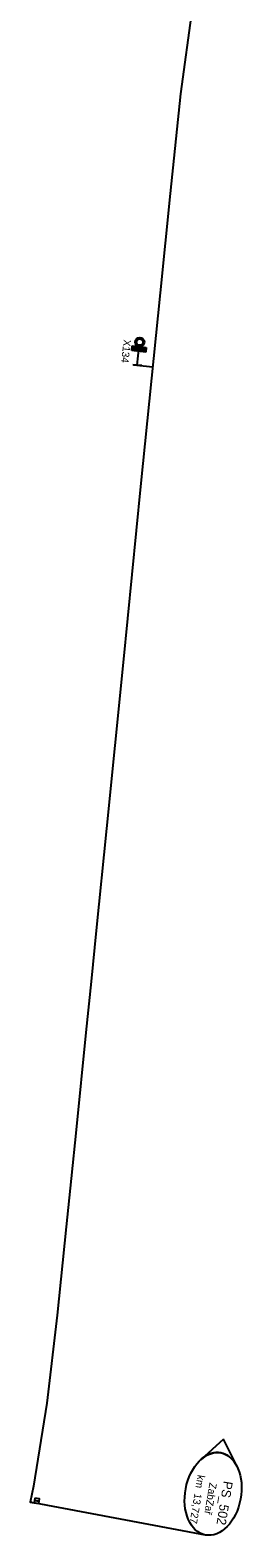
# Model space of a CAD drawing. Extents: x -743359 to -742769, y -1127804 to -1126284.
# Drawn here: x -743359.2 to -743301.5, y -1127804.4 to -1127398.7 of the extents above; entities that cross this region are included whole.
import ezdxf

# ---------------------------------------------------------------- set-up
doc = ezdxf.new("R2010")
doc.units = 0
for name, color, linetype in [('_Násyp', 7, 'Continuous'), ('_Zabezpečovací zařízení', 7, 'Continuous'), ('_Zabezpečovací zařízení_trasa', 7, 'Continuous'), ('bublina_růžová_230_čára_tenká', 7, 'Continuous'), ('bublina_růžová_230_čára_tučná', 7, 'Continuous')]:
    doc.layers.add(name, color=color, linetype=linetype)

msp = doc.modelspace()

# ---------------------------------------------------------------- linework, layer by layer
at = {"layer": '_Zabezpečovací zařízení'}
for p, q in [((-743331.88, -1127484.91), (-743331.75, -1127483.67)), ((-743331.88, -1127484.9), (-743330.52, -1127483.8)), ((-743328.15, -1127485.3), (-743331.88, -1127484.91)), ((-743331.82, -1127484.34), (-743331.08, -1127483.74)), ((-743331.76, -1127483.78), (-743331.64, -1127483.68)), ((-743331.75, -1127483.67), (-743328.02, -1127484.05)), ((-743331.34, -1127484.97), (-743329.96, -1127483.85)), ((-743330.78, -1127485.03), (-743329.94, -1127484.34)), ((-743330.4, -1127488.84), (-743329.89, -1127483.86)), ((-743330.22, -1127485.08), (-743330, -1127484.9)), ((-743330, -1127484.9), (-743328.85, -1127483.97)), ((-743329.94, -1127484.34), (-743329.41, -1127483.91)), ((-743329.66, -1127485.14), (-743328.29, -1127484.03)), ((-743329.1, -1127485.2), (-743328.05, -1127484.35)), ((-743328.54, -1127485.26), (-743328.11, -1127484.91)), ((-743328.02, -1127484.05), (-743328.15, -1127485.3)), ((-743329.16, -1127488.96), (-743331.64, -1127488.71)), ((-743357.94, -1127793.74), (-743358.15, -1127794.97)), ((-743358.15, -1127794.97), (-743356.92, -1127795.19)), ((-743356.81, -1127794.57), (-743358.04, -1127794.36)), ((-743356.71, -1127793.96), (-743357.94, -1127793.74)), ((-743356.92, -1127795.19), (-743356.71, -1127793.96))]:
    msp.add_line(p, q, dxfattribs=at)
msp.add_lwpolyline([(-743357.94, -1127793.74), (-743358.04, -1127794.36), (-743356.81, -1127794.57), (-743356.71, -1127793.96), (-743357.94, -1127793.74)], dxfattribs=at)
for radius in [1.25, 0.875]:
    msp.add_circle((-743329.76, -1127482.62), radius, dxfattribs=at)
at = {"layer": '_Zabezpečovací zařízení_trasa'}
for points in [[(-743315.69, -1127392.87), (-743318.79, -1127415.84), (-743321.57, -1127442.6), (-743324.27, -1127469.35), (-743329.51, -1127521.46), (-743334.23, -1127568.82), (-743338.71, -1127613.56), (-743341.47, -1127641), (-743342.85, -1127654.73), (-743344.22, -1127668.45), (-743346.84, -1127694.61), (-743348.17, -1127707.68), (-743349.5, -1127720.75), (-743351.96, -1127744.53), (-743354.76, -1127768.22), (-743358.32, -1127790.48), (-743359.2, -1127794.79), (-743358.15, -1127794.97)], [(-743331.4, -1127488.73), (-743326.22, -1127489.25)]]:
    msp.add_lwpolyline(points, dxfattribs=at)
at = {"layer": 'bublina_růžová_230_čára_tenká'}
msp.add_line((-743312.1, -1127803.66), (-743359.2, -1127794.79), dxfattribs=at)
at = {"layer": 'bublina_růžová_230_čára_tučná'}
for p, q in [((-743307.25, -1127777.86), (-743313.36, -1127783.41)), ((-743307.25, -1127777.86), (-743313.36, -1127783.41)), ((-743303.57, -1127785.25), (-743307.25, -1127777.86)), ((-743303.57, -1127785.25), (-743307.25, -1127777.86))]:
    msp.add_line(p, q, dxfattribs=at)
msp.add_ellipse((-743310.02, -1127792.6), major_axis=(-2.08, -11.06), ratio=0.666667, dxfattribs=at)
msp.add_ellipse((-743310.02, -1127792.6), major_axis=(2.08, 11.06), ratio=0.666473, start_param=5.557317, end_param=7.009053, dxfattribs=at)

# ---------------------------------------------------------------- texts
at = {"layer": '_Násyp'}
for s, height, p in [('km  13,727', 2, (-743314.18, -1127787.38)), ('ZabZař', 2, (-743310.98, -1127789.49)), ('PS_502', 2.5, (-743307.17, -1127789))]:
    msp.add_text(s, height=height, rotation=260.5528, dxfattribs=at).set_placement(p)
at = {"layer": '_Zabezpečovací zařízení'}
msp.add_text('X134', height=2, rotation=263.5157, dxfattribs=at).set_placement((-743334.07, -1127481.88))

doc.saveas('drawing.dxf')
